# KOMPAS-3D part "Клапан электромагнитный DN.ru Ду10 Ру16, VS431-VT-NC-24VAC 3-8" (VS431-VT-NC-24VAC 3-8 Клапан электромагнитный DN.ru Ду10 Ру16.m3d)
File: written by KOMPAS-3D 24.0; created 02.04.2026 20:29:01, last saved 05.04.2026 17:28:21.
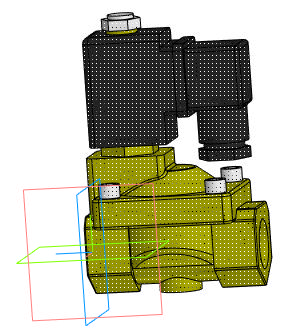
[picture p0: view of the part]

Document properties: Автор: artio; Полное имя файла: C:\Users\artio\OneDrive\Рабочий стол\Клапан электромагнитный DN.ru\VS431\VS431-VT-NC\VS431-VT-NC-24VAC\Ду10\VS431-VT-NC-24VAC 3-8 Клапан электромагнитный DN.ru Ду10 Ру16.m3d

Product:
- Body: Тело 1  | qty 1
    Масса: 1.030062
- Part/product: Клапан электромагнитный DN.ru Ду10 Ру16  | designation VS431-VT-NC-24VAC 3-8
    Масса: 0.62
    Раздел спецификации: Прочие изделия
    Примечание: D130-05638
    additional columns: ef56311e-7521-43dc-8291-0e6108b3d81d; VS400-ET-NC-220VAC 3-8; artio; c; Шероховатость не задана; Да

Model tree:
1. Операция без истории:1

Expressions: VS431-VT-NC-24VAC 3-8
